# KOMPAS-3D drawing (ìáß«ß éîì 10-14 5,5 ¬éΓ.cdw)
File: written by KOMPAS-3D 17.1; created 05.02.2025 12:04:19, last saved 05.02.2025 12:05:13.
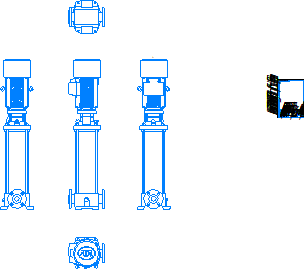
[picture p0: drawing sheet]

Sheet 1: A4, portrait

Title block, sheet 1: name: Насос ВМН 10-14 / 5,5 кВт; designation: Насос ВМН 10-14 5,5 кВт; material: Сталь 10  ГОСТ 1050-2013; mass: 233,01; sheets: 1; sheet format: A4; stored path: \\adlc.lan\data\АДЛ_ПКД\3D-модели\ADL production\Насосы ГРАНПАМП\Насосы ВМН\ВМН10\KOMPAS 3D\Насос ВМН 10-14 5,5 кВт.cdw

Views: Проекционный вид 2, Проекционный вид 3, Проекционный вид 4, Проекционный вид 5
Referenced files in \\adlc.lan\data\АДЛ_ПКД\3D-модели\ADL production\Насосы ГРАНПАМП\Насосы ВМН\ВМН10\KOMPAS 3D\: Насос ВМН 10-14 5,5 кВт.m3d
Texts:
  Andrey
  АДЛ
Dimensions and other numbers on the sheet: 1:1; 1; 5,5 кВт; 233,01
